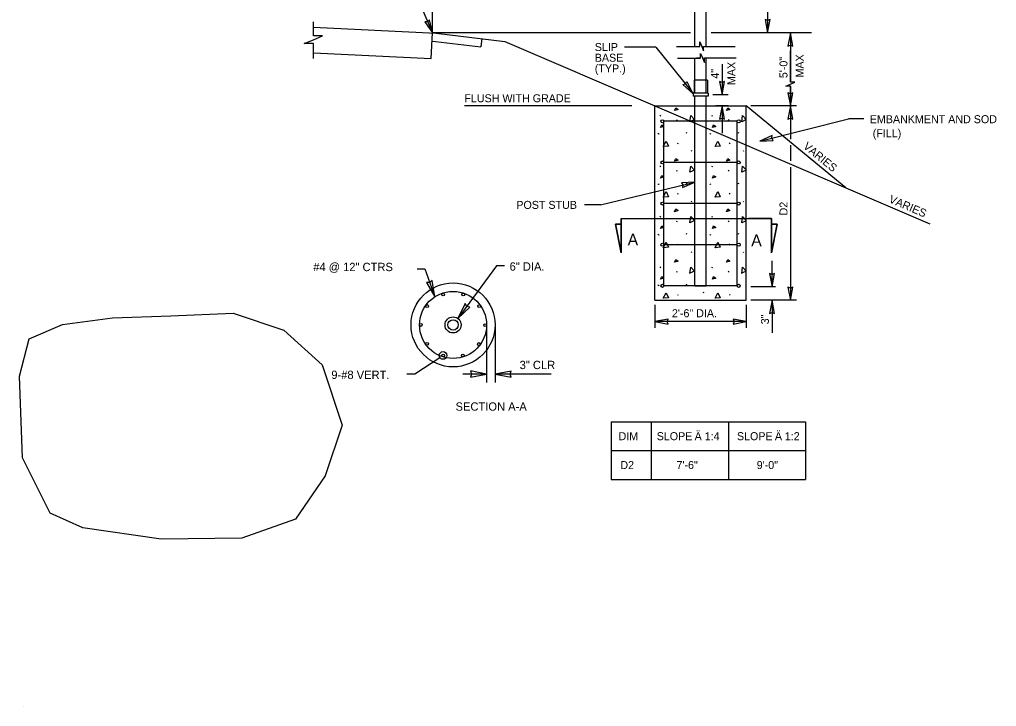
# Model space of a CAD drawing. Extents: x 52649 to 53276, y 9410 to 9783.
# Drawn here: x 52648.7 to 52969.2, y 9410 to 9635.5 of the extents above; entities that cross this region are included whole.
import ezdxf

# ---------------------------------------------------------------- set-up
doc = ezdxf.new("R2010")
doc.units = 0
for name, color, linetype in [('AdhocPoint_dp', 7, 'Continuous'), ('Default', 7, 'Continuous'), ('DimLines_dp', 7, 'Continuous'), ('LeaderLine_dp', 7, 'Continuous'), ('TextLabel', 7, 'Continuous'), ('TextTables', 7, 'Continuous')]:
    doc.layers.add(name, color=color, linetype=linetype)

msp = doc.modelspace()

# ---------------------------------------------------------------- linework, layer by layer
at = {"layer": 'AdhocPoint_dp'}
msp.add_line((52650, 9410), (52650, 9410), dxfattribs=at)
at = {"layer": 'Default'}
for p, q in [((52870.23, 9626.65), (52870.25, 9681.11)), ((52873.98, 9626.66), (52874, 9681.11)), ((52783.77, 9622.73), (52784.16, 9631.09)), ((52868.76, 9631.1), (52784.16, 9631.1)), ((52800.3, 9629.22), (52799.97, 9626.52)), ((52864.23, 9626.65), (52871.82, 9626.65)), ((52874.33, 9626.66), (52883.49, 9626.66)), ((52864.56, 9622.85), (52872.14, 9622.85)), ((52870.23, 9615.61), (52870.23, 9622.85)), ((52873.98, 9615.61), (52873.98, 9622.85)), ((52874.66, 9622.86), (52883.81, 9622.86)), ((52869.96, 9615.61), (52869.96, 9611.29)), ((52874.34, 9615.61), (52869.96, 9615.61)), ((52870.24, 9611.29), (52870.24, 9615.61)), ((52873.99, 9611.29), (52873.99, 9615.61)), ((52874.34, 9615.61), (52874.34, 9611.29)), ((52869.65, 9611.29), (52869.65, 9610.36)), ((52874.65, 9611.29), (52869.65, 9611.29)), ((52874.65, 9610.35), (52869.65, 9610.35)), ((52870.22, 9548.08), (52870.24, 9610.36)), ((52873.97, 9548.08), (52873.99, 9610.36)), ((52874.65, 9611.29), (52874.65, 9610.36)), ((52857.11, 9607.15), (52887.11, 9607.14)), ((52857.11, 9543.35), (52857.11, 9607.15)), ((52857.11, 9603.58), (52857.11, 9607.15)), ((52857.11, 9607.15), (52919.81, 9580.23)), ((52887.11, 9543.35), (52887.11, 9607.14)), ((52919.81, 9580.23), (52887.11, 9607.14)), ((52858.88, 9603.77), (52859.02, 9604.09)), ((52875.89, 9603.77), (52876.04, 9604.09)), ((52884.11, 9602.08), (52860.11, 9602.08)), ((52860.11, 9548.08), (52860.11, 9602.08)), ((52864.28, 9602.31), (52864.42, 9602.63)), ((52881.29, 9602.31), (52881.44, 9602.63)), ((52884.11, 9548.08), (52884.11, 9602.08)), ((52858.13, 9598.19), (52858.27, 9597.98)), ((52858.27, 9598.11), (52858.42, 9597.89)), ((52867.51, 9598.19), (52867.65, 9598.51)), ((52875.15, 9598.19), (52875.29, 9597.98)), ((52875.29, 9598.11), (52875.43, 9597.89)), ((52884.53, 9598.19), (52884.67, 9598.51)), ((52864.63, 9594.74), (52864.78, 9595.06)), ((52881.65, 9594.74), (52881.79, 9595.06)), ((52869.07, 9592.47), (52869.22, 9592.25)), ((52886.09, 9592.47), (52886.23, 9592.25)), ((52858.88, 9587.17), (52859.02, 9587.49)), ((52884.11, 9588.58), (52860.11, 9588.58)), ((52875.89, 9587.17), (52876.04, 9587.49)), ((52864.28, 9585.72), (52864.42, 9586.04)), ((52881.29, 9585.72), (52881.44, 9586.04)), ((52858.13, 9581.6), (52858.27, 9581.38)), ((52858.27, 9581.52), (52858.42, 9581.3)), ((52867.51, 9581.6), (52867.65, 9581.92)), ((52875.15, 9581.6), (52875.29, 9581.38)), ((52875.29, 9581.52), (52875.43, 9581.3)), ((52884.53, 9581.6), (52884.67, 9581.92)), ((52864.63, 9578.15), (52864.78, 9578.47)), ((52881.65, 9578.15), (52881.79, 9578.47)), ((52919.81, 9580.23), (52947.38, 9568.4)), ((52884.11, 9575.08), (52860.11, 9575.08)), ((52869.07, 9575.87), (52869.22, 9575.66)), ((52886.09, 9575.87), (52886.23, 9575.66)), ((52846.03, 9558.96), (52844.16, 9568.33)), ((52844.16, 9568.33), (52846.03, 9568.33)), ((52846.03, 9570.21), (52846.03, 9558.96)), ((52846.03, 9568.33), (52846.03, 9570.21)), ((52846.03, 9570.21), (52853.53, 9570.21)), ((52851.97, 9570.21), (52895.38, 9570.21)), ((52858.88, 9570.58), (52859.02, 9570.9)), ((52864.28, 9569.12), (52864.42, 9569.44)), ((52875.89, 9570.58), (52876.04, 9570.9)), ((52881.29, 9569.12), (52881.44, 9569.44)), ((52895.38, 9570.21), (52887.88, 9570.21)), ((52895.38, 9570.21), (52895.38, 9558.96)), ((52895.38, 9568.33), (52895.38, 9570.21)), ((52895.38, 9558.96), (52897.25, 9568.33)), ((52897.25, 9568.33), (52895.38, 9568.33)), ((52858.13, 9565), (52858.27, 9564.79)), ((52858.27, 9564.92), (52858.42, 9564.71)), ((52867.51, 9565), (52867.65, 9565.32)), ((52875.15, 9565), (52875.29, 9564.79)), ((52875.29, 9564.92), (52875.43, 9564.71)), ((52884.53, 9565), (52884.67, 9565.32)), ((52884.11, 9561.58), (52860.11, 9561.58)), ((52864.63, 9561.55), (52864.78, 9561.87)), ((52881.65, 9561.55), (52881.79, 9561.87)), ((52869.07, 9559.28), (52869.22, 9559.07)), ((52886.09, 9559.28), (52886.23, 9559.07)), ((52858.88, 9553.99), (52859.02, 9554.31)), ((52864.28, 9552.53), (52864.42, 9552.85)), ((52875.89, 9553.99), (52876.04, 9554.31)), ((52881.29, 9552.53), (52881.44, 9552.85)), ((52867.51, 9548.41), (52867.65, 9548.73)), ((52884.53, 9548.41), (52884.67, 9548.73)), ((52858.13, 9548.41), (52858.27, 9548.2)), ((52858.27, 9548.33), (52858.42, 9548.12)), ((52884.11, 9548.08), (52860.11, 9548.08)), ((52870.22, 9548.08), (52873.97, 9548.08)), ((52873.05, 9545.78), (52873.19, 9546.1)), ((52875.15, 9548.41), (52875.29, 9548.2)), ((52875.29, 9548.33), (52875.43, 9548.12)), ((52896.72, 9547.79), (52888.61, 9547.79)), ((52857.11, 9543.35), (52887.11, 9543.35)), ((52864.63, 9544.96), (52864.78, 9545.28)), ((52881.65, 9544.96), (52881.79, 9545.28))]:
    msp.add_line(p, q, dxfattribs=at)
for points in [[(52745.07, 9622.71), (52745.07, 9627.57), (52742.09, 9627.57), (52745.07, 9628.87), (52748.05, 9630.16), (52745.07, 9630.16), (52745.07, 9634.77)], [(52745.07, 9632.95), (52785.34, 9631.04), (52807.84, 9628.3)], [(52784.03, 9628.38), (52785.11, 9628.33), (52799.97, 9626.52)], [(52807.84, 9628.3), (52857.11, 9607.15)], [(52870.43, 9626.66), (52871.82, 9626.66), (52871.82, 9628.15), (52872.47, 9626.66), (52873.11, 9625.17), (52873.11, 9626.66), (52874.51, 9626.66)], [(52745.07, 9624.57), (52783.77, 9622.73)], [(52870.75, 9622.86), (52872.14, 9622.86), (52872.14, 9624.35), (52872.79, 9622.86), (52873.44, 9621.37), (52873.44, 9622.86), (52874.83, 9622.86)], [(52863.57, 9605.6), (52864, 9606.48), (52864.71, 9605.95), (52863.57, 9605.6)], [(52880.59, 9605.6), (52881.02, 9606.48), (52881.73, 9605.95), (52880.59, 9605.6)], [(52868.6, 9601.94), (52868.88, 9603.97), (52870.15, 9602.66), (52868.63, 9601.95)], [(52885.61, 9601.94), (52885.9, 9603.97), (52887.11, 9602.72)], [(52858.95, 9600.04), (52859.38, 9600.92), (52860.09, 9600.39), (52858.95, 9600.04)], [(52875.97, 9600.04), (52876.39, 9600.92), (52877.1, 9600.39), (52875.97, 9600.04)], [(52887.11, 9602.63), (52885.65, 9601.95)], [(52859.84, 9593.78), (52860.8, 9595.59), (52861.54, 9593.92), (52859.87, 9593.78)], [(52876.85, 9593.78), (52877.81, 9595.59), (52878.56, 9593.92), (52876.89, 9593.78)], [(52863.57, 9589), (52864, 9589.89), (52864.71, 9589.36), (52863.57, 9589)], [(52868.6, 9585.35), (52868.88, 9587.38), (52870.15, 9586.07), (52868.63, 9585.36)], [(52880.59, 9589), (52881.02, 9589.89), (52881.73, 9589.36), (52880.59, 9589)], [(52885.61, 9585.35), (52885.9, 9587.38), (52887.11, 9586.13)], [(52858.95, 9583.44), (52859.38, 9584.33), (52860.09, 9583.8), (52858.95, 9583.44)], [(52875.97, 9583.44), (52876.39, 9584.33), (52877.1, 9583.8), (52875.97, 9583.44)], [(52887.11, 9586.04), (52885.65, 9585.36)], [(52859.84, 9577.19), (52860.8, 9579), (52861.54, 9577.33), (52859.87, 9577.19)], [(52876.85, 9577.19), (52877.81, 9579), (52878.56, 9577.33), (52876.89, 9577.19)], [(52863.57, 9572.41), (52864, 9573.3), (52864.71, 9572.77), (52863.57, 9572.41)], [(52880.59, 9572.41), (52881.02, 9573.3), (52881.73, 9572.77), (52880.59, 9572.41)], [(52868.6, 9568.76), (52868.88, 9570.79), (52870.15, 9569.47), (52868.63, 9568.77)], [(52885.61, 9568.76), (52885.9, 9570.79), (52887.11, 9569.54)], [(52887.11, 9569.45), (52885.65, 9568.77)], [(52858.95, 9566.85), (52859.38, 9567.74), (52860.09, 9567.21), (52858.95, 9566.85)], [(52875.97, 9566.85), (52876.39, 9567.74), (52877.1, 9567.21), (52875.97, 9566.85)], [(52859.84, 9560.59), (52860.8, 9562.41), (52861.54, 9560.74), (52859.87, 9560.59)], [(52876.85, 9560.59), (52877.81, 9562.41), (52878.56, 9560.74), (52876.89, 9560.59)], [(52863.57, 9555.82), (52864, 9556.71), (52864.71, 9556.17), (52863.57, 9555.82)], [(52880.59, 9555.82), (52881.02, 9556.71), (52881.73, 9556.17), (52880.59, 9555.82)], [(52868.6, 9552.16), (52868.88, 9554.19), (52870.15, 9552.88), (52868.63, 9552.18)], [(52885.61, 9552.16), (52885.9, 9554.19), (52887.11, 9552.94)], [(52887.11, 9552.85), (52885.65, 9552.18)], [(52858.95, 9550.26), (52859.38, 9551.15), (52860.09, 9550.61), (52858.95, 9550.26)], [(52875.97, 9550.26), (52876.39, 9551.15), (52877.1, 9550.61), (52875.97, 9550.26)], [(52859.84, 9544), (52860.8, 9545.81), (52861.54, 9544.14), (52859.87, 9544)], [(52876.85, 9544), (52877.81, 9545.81), (52878.56, 9544.14), (52876.89, 9544)]]:
    msp.add_lwpolyline(points, dxfattribs=at)
for points in [[(52846.03, 9568.33), (52844.16, 9568.33), (52846.03, 9558.96)], [(52897.25, 9568.33), (52895.38, 9558.96), (52895.38, 9568.33)]]:
    msp.add_lwpolyline(points, close=True, dxfattribs=at)
for centre, radius in [((52859.61, 9602.08), 0.5), ((52884.61, 9602.08), 0.5), ((52859.61, 9588.58), 0.5), ((52884.61, 9588.58), 0.5), ((52859.61, 9575.08), 0.5), ((52884.61, 9575.08), 0.5), ((52859.61, 9561.58), 0.5), ((52884.61, 9561.58), 0.5), ((52790.9, 9535.24), 13.77), ((52790.9, 9535.24), 11.01), ((52787.64, 9545.28), 0.459), ((52794.25, 9545.26), 0.459), ((52859.61, 9548.08), 0.5), ((52884.61, 9548.08), 0.5), ((52782.36, 9541.45), 0.459), ((52799.5, 9541.38), 0.459), ((52790.9, 9535.24), 2.64), ((52790.9, 9535.24), 1.72), ((52780.34, 9535.24), 0.459), ((52801.46, 9535.16), 0.459), ((52782.36, 9529.04), 0.459), ((52799.39, 9528.97), 0.459), ((52787.64, 9525.21), 0.459), ((52794.08, 9525.18), 0.459)]:
    msp.add_circle(centre, radius, dxfattribs=at)
at = {"layer": 'DimLines_dp'}
for p, q in [((52784.16, 9631.1), (52784.11, 9744.33)), ((52894.07, 9681.11), (52894.07, 9631.1)), ((52778.34, 9644.48), (52784.16, 9631.09)), ((52783.19, 9635.42), (52782.56, 9634.78)), ((52784.16, 9631.09), (52783.19, 9635.42)), ((52894.07, 9635.12), (52893.26, 9635.45)), ((52893.26, 9635.45), (52894.07, 9631.1)), ((52894.07, 9631.1), (52894.91, 9635.45)), ((52894.91, 9635.45), (52894.07, 9635.12)), ((52782.56, 9634.78), (52781.68, 9634.76)), ((52781.68, 9634.76), (52784.16, 9631.09)), ((52908.52, 9631.1), (52875.58, 9631.1)), ((52901.58, 9631.1), (52900.74, 9626.75)), ((52902.39, 9626.75), (52901.58, 9631.1)), ((52901.58, 9631.1), (52901.58, 9614.88)), ((52857.41, 9626.47), (52847.19, 9626.47)), ((52857.41, 9626.47), (52869.65, 9611.2)), ((52900.74, 9626.75), (52901.58, 9627.08)), ((52901.58, 9627.08), (52902.39, 9626.75)), ((52901.58, 9616.1), (52901.57, 9625.26)), ((52879.15, 9620.82), (52879.15, 9610.82)), ((52866.26, 9614.17), (52867.13, 9614.42)), ((52869.58, 9611.24), (52866.26, 9614.17)), ((52867.13, 9614.42), (52867.57, 9615.18)), ((52867.57, 9615.18), (52869.58, 9611.24)), ((52879.15, 9614.84), (52878.34, 9615.17)), ((52878.34, 9615.17), (52879.15, 9610.82)), ((52879.15, 9610.82), (52879.99, 9615.17)), ((52879.99, 9615.17), (52879.15, 9614.84)), ((52901.58, 9613.58), (52901.58, 9607.13)), ((52901.59, 9606), (52901.59, 9613.58)), ((52881.15, 9610.82), (52876.15, 9610.82)), ((52901.58, 9611.15), (52900.77, 9611.48)), ((52900.77, 9611.48), (52901.58, 9607.13)), ((52901.58, 9607.13), (52902.42, 9611.48)), ((52902.42, 9611.48), (52901.58, 9611.15)), ((52849.61, 9607.15), (52794.61, 9607.15)), ((52881.15, 9607.15), (52877.15, 9607.15)), ((52879.15, 9607.15), (52878.31, 9602.8)), ((52879.96, 9602.8), (52879.15, 9607.15)), ((52879.15, 9607.15), (52879.15, 9598.15)), ((52903.58, 9607.13), (52888.61, 9607.13)), ((52901.58, 9607.13), (52900.74, 9602.78)), ((52902.39, 9602.78), (52901.58, 9607.13)), ((52901.58, 9607.13), (52901.58, 9596.23)), ((52878.31, 9602.8), (52879.15, 9603.13)), ((52879.15, 9603.13), (52879.96, 9602.8)), ((52891.55, 9595.55), (52920.63, 9602.87)), ((52900.74, 9602.78), (52901.58, 9603.11)), ((52901.58, 9603.11), (52902.39, 9602.78)), ((52925.63, 9602.87), (52920.63, 9602.87)), ((52895.57, 9597.4), (52891.55, 9595.55)), ((52895.45, 9596.53), (52895.57, 9597.4)), ((52891.55, 9595.55), (52895.98, 9595.8)), ((52895.98, 9595.8), (52895.45, 9596.53)), ((52901.58, 9594.23), (52901.58, 9589.06)), ((52901.58, 9587.06), (52901.58, 9543.34)), ((52839.26, 9574.63), (52870.23, 9582.12)), ((52870.23, 9582.12), (52865.8, 9581.92)), ((52865.8, 9581.92), (52866.32, 9581.18)), ((52866.19, 9580.31), (52870.23, 9582.12)), ((52866.32, 9581.18), (52866.19, 9580.31)), ((52839.26, 9574.63), (52834.08, 9574.63)), ((52895.56, 9547.79), (52895.56, 9556.27)), ((52895.56, 9551.81), (52894.75, 9552.14)), ((52894.75, 9552.14), (52895.56, 9547.79)), ((52895.56, 9547.79), (52896.4, 9552.14)), ((52896.4, 9552.14), (52895.56, 9551.81)), ((52901.58, 9547.36), (52900.77, 9547.69)), ((52900.77, 9547.69), (52901.58, 9543.34)), ((52901.58, 9543.34), (52902.42, 9547.69)), ((52902.42, 9547.69), (52901.58, 9547.36)), ((52903.58, 9543.34), (52888.61, 9543.34)), ((52895.56, 9543.34), (52894.72, 9538.99)), ((52895.56, 9543.34), (52895.56, 9532.64)), ((52896.37, 9538.99), (52895.56, 9543.34)), ((52857.11, 9541.85), (52857.11, 9534.32)), ((52887.11, 9541.84), (52887.11, 9534.32)), ((52894.72, 9538.99), (52895.56, 9539.32)), ((52895.56, 9539.32), (52896.37, 9538.99)), ((52861.46, 9537.13), (52857.11, 9536.32)), ((52887.11, 9536.32), (52857.11, 9536.32)), ((52857.11, 9536.32), (52861.46, 9535.48)), ((52861.13, 9536.32), (52861.46, 9537.13)), ((52861.46, 9535.48), (52861.13, 9536.32)), ((52887.11, 9536.32), (52882.76, 9537.16)), ((52882.76, 9537.16), (52883.09, 9536.32)), ((52883.09, 9536.32), (52882.76, 9535.51)), ((52882.76, 9535.51), (52887.11, 9536.32))]:
    msp.add_line(p, q, dxfattribs=at)
msp.add_lwpolyline([(52901.58, 9612.19), (52901.58, 9613.58), (52900.09, 9613.58), (52901.58, 9614.23), (52903.07, 9614.88), (52901.58, 9614.88), (52901.58, 9616.27)], dxfattribs=at)
at = {"layer": 'LeaderLine_dp'}
for p, q in [((52783.26, 9549.12), (52782.19, 9549.17)), ((52782.19, 9549.17), (52784.89, 9544.47)), ((52784.09, 9549.84), (52783.26, 9549.12)), ((52784.89, 9544.47), (52784.09, 9549.84)), ((52794.82, 9542.25), (52792.46, 9537.37)), ((52792.46, 9537.37), (52796.44, 9541.05)), ((52795.38, 9541.34), (52794.82, 9542.25)), ((52796.44, 9541.05), (52795.38, 9541.34)), ((52801.92, 9535.24), (52801.92, 9516.32)), ((52804.67, 9535.24), (52804.67, 9516.32)), ((52801.92, 9519.09), (52796.59, 9520.12)), ((52796.59, 9520.12), (52797, 9519.09)), ((52809.99, 9520.08), (52804.67, 9519.09)), ((52809.59, 9519.09), (52809.99, 9520.08)), ((52801.92, 9519.09), (52794.16, 9519.09)), ((52797, 9519.09), (52796.59, 9518.1)), ((52796.59, 9518.1), (52801.92, 9519.09)), ((52823.07, 9519.09), (52804.67, 9519.09)), ((52804.67, 9519.09), (52809.99, 9518.06)), ((52809.99, 9518.06), (52809.59, 9519.09))]:
    msp.add_line(p, q, dxfattribs=at)
for points in [[(52779.09, 9553.69), (52781.65, 9553.69), (52784.89, 9544.47)], [(52807.74, 9554.68), (52805.18, 9554.68), (52792.46, 9537.37)], [(52775.77, 9519.19), (52778.32, 9519.19), (52786.55, 9524.56)]]:
    msp.add_lwpolyline(points, dxfattribs=at)
msp.add_circle((52787.64, 9525.21), 1.26, dxfattribs=at)
at = {"layer": 'TextLabel'}
msp.add_lwpolyline([(52651.8, 9530.64), (52662.8, 9535.36), (52679.14, 9537.56), (52698.31, 9538.19), (52718.73, 9539.13), (52735.38, 9533.47), (52747.95, 9522.15), (52754.55, 9502.34), (52748.9, 9485.67), (52739.15, 9471.52), (52721.56, 9465.23), (52695.16, 9464.92), (52669.4, 9468.69), (52658.71, 9473.41), (52649.6, 9491.65), (52648.66, 9518.38), (52651.8, 9530.64)], dxfattribs=at)
at = {"layer": 'TextTables'}
for p, q in [((52842.74, 9503.46), (52842.74, 9484.51)), ((52842.74, 9503.46), (52906.59, 9503.46)), ((52855.87, 9503.46), (52855.87, 9484.51)), ((52881.23, 9503.46), (52881.23, 9484.51)), ((52906.59, 9503.46), (52906.59, 9484.51)), ((52842.74, 9493.99), (52906.59, 9493.99)), ((52842.74, 9484.51), (52906.59, 9484.51))]:
    msp.add_line(p, q, dxfattribs=at)

# ---------------------------------------------------------------- texts
at = {"layer": 'Default'}
for s, height, rotation, p in [('VARIES', 2.625, 320.5514, (52905.58, 9593.47)), ('VARIES', 2.625, 336.7682, (52933.69, 9575.56)), ('#4 @ 12" CTRS', 2.7344, 0, (52745.01, 9552.9)), ('6" DIA.', 2.734, 0, (52809.45, 9553.06)), ('3" CLR', 2.734, 0, (52812.74, 9520.74)), ('9-#8 VERT.', 2.734, 0, (52750.95, 9517.5)), ('SECTION A-A', 2.7344, 0, (52791.72, 9507.09))]:
    msp.add_text(s, height=height, rotation=rotation, dxfattribs=at).set_placement(p)
for p in [(52848.2, 9561.36), (52888.73, 9561.09)]:
    msp.add_text('A', height=3.84, dxfattribs=at).set_placement(p)
at = {"layer": 'DimLines_dp'}
for s, p in [('SLIP', (52837.4, 9625.15)), ('BASE', (52837.4, 9621.64)), ('(TYP.)', (52837.4, 9618.12)), ('FLUSH WITH GRADE', (52794.61, 9608.33)), ('EMBANKMENT AND SOD', (52927.62, 9601.46)), (' (FILL)', (52927.62, 9596.87)), ('POST STUB', (52811.66, 9573.33)), ('2\'-6" DIA.', (52862.71, 9537.77))]:
    msp.add_text(s, height=2.625, dxfattribs=at).set_placement(p)
for s, p in [('5\'-0"', (52900.62, 9616.24)), ('MAX', (52905.95, 9616.45)), ('MAX', (52883.53, 9613.98)), ('4"', (52878.15, 9616.07)), ('D2', (52900.63, 9571.18)), ('3"', (52894.54, 9535.45))]:
    msp.add_text(s, height=2.625, rotation=90, dxfattribs=at).set_placement(p)
at = {"layer": 'TextTables'}
for s, height, p in [('Ä', 2.63, (52870.15, 9497.41)), ('Ä', 2.63, (52896.49, 9497.41)), ('DIM', 2.625, (52845.2, 9497.41)), ('SLOPE ', 2.625, (52857.71, 9497.41)), ('1:4', 2.625, (52873.46, 9497.41)), ('SLOPE ', 2.625, (52884.04, 9497.41)), ('1:2', 2.625, (52899.74, 9497.41)), ('D2', 2.625, (52845.79, 9487.94)), ('7\'-6"', 2.625, (52864.2, 9487.94)), ('9\'-0"', 2.625, (52890.53, 9487.94))]:
    msp.add_text(s, height=height, dxfattribs=at).set_placement(p)

doc.saveas('drawing.dxf')
